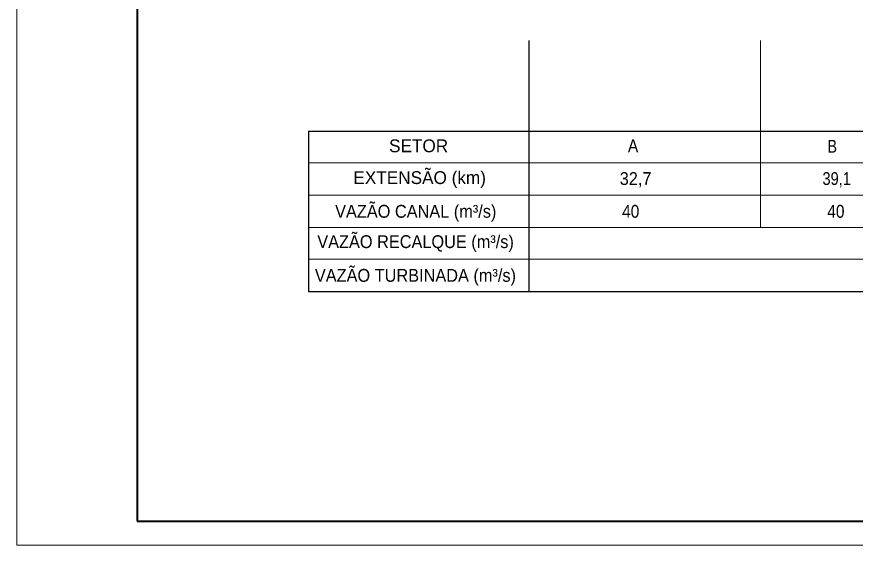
# Model space of a CAD drawing. Extents: x 8426.2 to 8495.4, y 19933.5 to 19963.2.
# Drawn here: x 8426.17 to 8443.58, y 19933.55 to 19944.52 of the extents above; entities that cross this region are included whole.
import ezdxf

# ---------------------------------------------------------------- set-up
doc = ezdxf.new("R2010")
doc.units = 0
doc.header["$LTSCALE"] = 0.11
doc.layers.add('1', color=7, linetype='Continuous', lineweight=35)
doc.layers.add('3', color=7, linetype='Continuous', lineweight=25)

msp = doc.modelspace()

# ---------------------------------------------------------------- linework, layer by layer
at = {"layer": '1', "lineweight": 13}
msp.add_lwpolyline([(8426.17, 19933.55), (8495.44, 19933.55), (8495.44, 19963.25), (8426.17, 19963.25)], close=True, dxfattribs=at)
at = {"layer": '1', "lineweight": 40}
for points in [[(8428.67, 19934.05), (8494.94, 19934.05), (8494.94, 19962.75)], [(8494.94, 19962.75), (8428.67, 19962.75), (8428.67, 19934.05)]]:
    msp.add_lwpolyline(points, dxfattribs=at)
at = {"layer": '3'}
for p, q in [((8436.8, 19944.03), (8436.8, 19938.82)), ((8432.23, 19942.15), (8432.23, 19938.82)), ((8432.23, 19942.15), (8490.75, 19942.15)), ((8432.23, 19938.82), (8490.75, 19938.82))]:
    msp.add_line(p, q, dxfattribs=at)
at = {"layer": '3', "lineweight": 13}
for p, q in [((8441.61, 19944.03), (8441.61, 19940.15)), ((8432.23, 19941.49), (8490.75, 19941.49)), ((8432.23, 19940.82), (8490.75, 19940.82)), ((8432.23, 19940.15), (8490.75, 19940.15)), ((8433.47, 19940.15), (8490.75, 19940.15)), ((8432.23, 19939.49), (8490.75, 19939.49))]:
    msp.add_line(p, q, dxfattribs=at)

# ---------------------------------------------------------------- texts
at = {"layer": '3'}
for s, p in [('SETOR', (8433.9, 19941.71)), ('EXTENSÃO (km)', (8433.16, 19941.05))]:
    msp.add_text(s, height=0.2665, dxfattribs=at).set_placement(p)
for s, height, width, p in [('A', 0.267, 0.9, (8438.86, 19941.71)), ('B', 0.267, 0.85, (8443, 19941.7)), ('32,7', 0.2665, 0.95, (8438.69, 19941.03)), ('39,1', 0.2665, 0.85, (8442.9, 19941.03)), ('VAZÃO CANAL (m³/s)', 0.2665, 0.95, (8432.78, 19940.35)), ('40', 0.2665, 0.9, (8438.74, 19940.35)), ('40', 0.2665, 0.9, (8443, 19940.35)), ('VAZÃO RECALQUE (m³/s)', 0.2665, 0.95, (8432.41, 19939.72)), ('VAZÃO TURBINADA (m³/s)', 0.2665, 0.95, (8432.36, 19939.02))]:
    msp.add_text(s, height=height, dxfattribs=dict(at, width=width)).set_placement(p)

doc.saveas('drawing.dxf')
